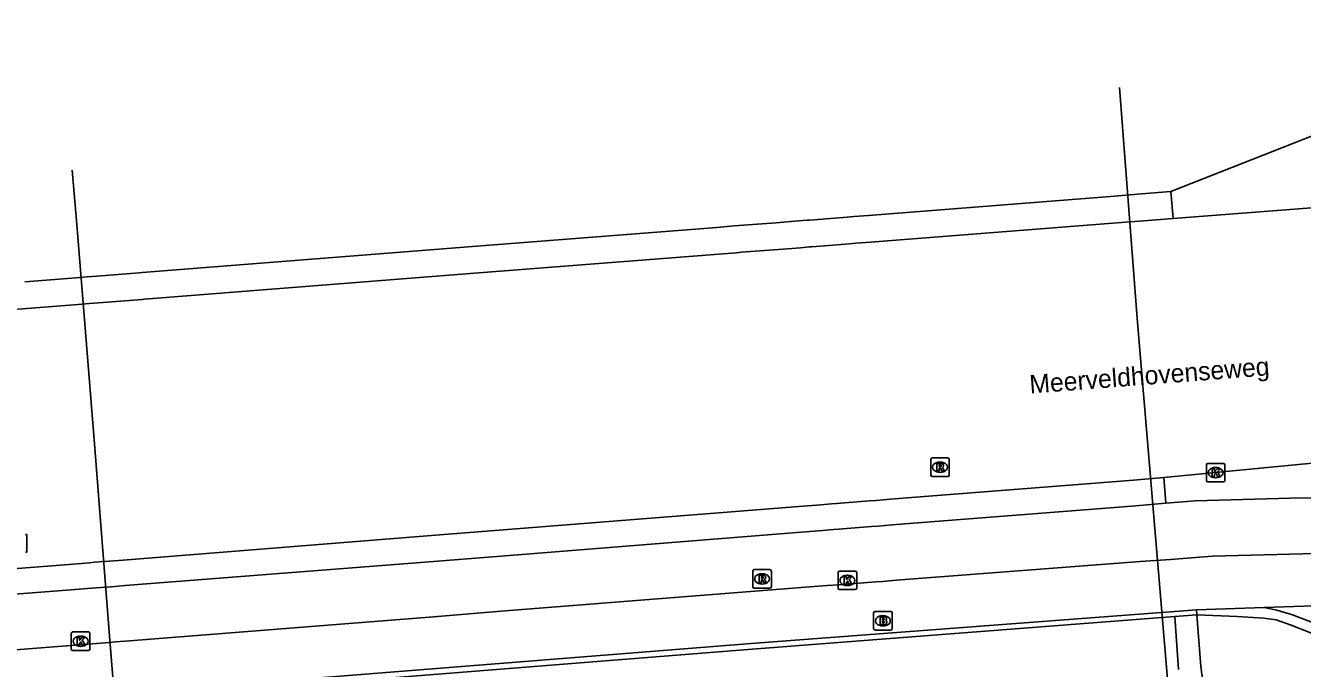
# Model space of a CAD drawing. Extents: x 157663 to 158496, y 379212 to 380934.
# Drawn here: x 157892.7 to 157961.7, y 380858 to 380892.7 of the extents above; entities that cross this region are included whole.
import ezdxf

# ---------------------------------------------------------------- set-up
doc = ezdxf.new("R2010")
doc.units = 0
for name, color, linetype in [('IMGEO_Berm_groen', 7, 'Continuous'), ('IMGEO_Berm_open', 7, 'Continuous'), ('IMGEO_Brandkraan', 7, 'Continuous'), ('IMGEO_Fietspad_gesloten', 7, 'Continuous'), ('IMGEO_Geluidsscherm', 7, 'Continuous'), ('IMGEO_Kolk', 7, 'Continuous'), ('IMGEO_Muur', 7, 'Continuous'), ('IMGEO_Openbare_ruimte_label', 7, 'Continuous'), ('IMGEO_Rijbaan_regionaal_gesloten', 7, 'Continuous'), ('IMGEO_Rioolput', 7, 'Continuous'), ('IMGEO_Terreindeel_gesloten', 7, 'Continuous'), ('IMGEO_Voetpad_open', 7, 'Continuous')]:
    doc.layers.add(name, color=color, linetype=linetype)

msp = doc.modelspace()

# ---------------------------------------------------------------- linework, layer by layer
at = {"layer": 'IMGEO_Berm_groen'}
for points in [[(157956.001, 380860.869), (157958.182, 380860.771), (157959.629, 380860.683), (157960.287, 380860.587), (157961.097, 380860.31), (157962.201, 380859.875), (157963.271, 380859.386), (157964.245, 380858.856), (157964.883, 380858.4), (157965.621, 380857.734), (157966.172, 380857.042), (157966.889, 380856.044), (157967.537, 380854.98), (157967.998, 380854.077), (157968.335, 380853.169), (157968.683, 380851.984), (157969.15, 380850.168)], [(157969.15, 380850.168), (157969.673, 380850.29), (157969.424, 380851.247), (157969.04, 380852.627), (157968.658, 380853.757), (157968.264, 380854.734), (157967.78, 380855.555), (157967.144, 380856.557), (157966.494, 380857.451), (157965.917, 380858.133), (157965.187, 380858.817), (157964.447, 380859.349), (157963.363, 380859.945), (157962.247, 380860.451), (157961.18, 380860.86), (157960.327, 380861.109), (157959.639, 380861.264)]]:
    msp.add_lwpolyline(points, dxfattribs=at)
at = {"layer": 'IMGEO_Berm_open'}
for points in [[(157954.819, 380860.777), (157931.957, 380859.016), (157909.091, 380857.181), (157878.581, 380854.843)], [(157956.001, 380860.869), (157954.819, 380860.777)], [(157955.012, 380857.901), (157954.819, 380860.777)], [(157956.959, 380852.419), (157956.217, 380858.075), (157956.001, 380860.869)]]:
    msp.add_lwpolyline(points, dxfattribs=at)
at = {"layer": 'IMGEO_Brandkraan'}
for p, q in [((157938.532, 380860.115), (157938.532, 380860.967)), ((157938.607, 380861.041), (157939.459, 380861.041)), ((157939.02, 380860.821), (157939.045, 380860.821)), ((157939.533, 380860.967), (157939.533, 380860.115)), ((157939.459, 380860.041), (157938.607, 380860.041)), ((157939.043, 380860.261), (157939.018, 380860.261))]:
    msp.add_line(p, q, dxfattribs=at)
for points in [[(157938.532, 380860.115), (157938.532, 380860.967)], [(157938.607, 380861.041), (157939.459, 380861.041)], [(157938.88, 380860.741), (157938.88, 380860.341), (157939.093, 380860.341)], [(157939.111, 380860.741), (157938.88, 380860.741)], [(157939.059, 380860.66), (157939.005, 380860.66), (157939.005, 380860.584)], [(157939.533, 380860.967), (157939.533, 380860.115)], [(157939.459, 380860.041), (157938.607, 380860.041)], [(157939.005, 380860.584), (157939.058, 380860.584)], [(157939.067, 380860.508), (157939.005, 380860.508), (157939.005, 380860.427)], [(157939.005, 380860.427), (157939.067, 380860.427)]]:
    msp.add_lwpolyline(points, dxfattribs=at)
for centre, radius, start, end in [((157938.609, 380860.965), 0.0765, 91.55205, 178.44795), ((157938.609, 380860.965), 0.0765, 91.55205, 178.44795), ((157939.06, 380860.622), 0.0379, 267.82845, 90.93552), ((157939.115, 380860.596), 0.145, 59.4692, 91.53667), ((157939.14, 380860.643), 0.0922, 285.51372, 58.15012), ((157939.457, 380860.965), 0.0765, 1.55205, 88.44795), ((157939.457, 380860.965), 0.0765, 1.55205, 88.44795), ((157938.609, 380860.117), 0.0765, 181.55205, 268.44795), ((157938.609, 380860.117), 0.0765, 181.55205, 268.44795), ((157939.068, 380860.467), 0.0404, 269.87594, 90.50774), ((157939.099, 380860.592), 0.251, 268.66757, 293.53466), ((157939.145, 380860.451), 0.105, 301.31148, 78.98903), ((157939.457, 380860.117), 0.0765, 271.55205, 358.44795), ((157939.457, 380860.117), 0.0765, 271.55205, 358.44795)]:
    msp.add_arc(centre, radius, start, end, dxfattribs=at)
for centre, major_axis, ratio, start_param, end_param in [((157939.019, 380860.541), (-0.387, 0.002), 0.722429, 4.712389, 7.853982), ((157939.044, 380860.541), (-0.39, 0.002), 0.717154, 1.570796, 4.712389)]:
    msp.add_ellipse(centre, major_axis=major_axis, ratio=ratio, start_param=start_param, end_param=end_param, dxfattribs=at)
at = {"layer": 'IMGEO_Fietspad_gesloten'}
for points in [[(157954.335, 380866.896), (157955.904, 380867.02), (157961.7, 380867.19), (157971.149, 380867.041), (157975.69, 380866.578), (157981.329, 380865.841), (157983.738, 380865.449), (157988.713, 380864.866), (157991.034, 380864.672), (157993.535, 380864.574), (157998.608, 380864.538), (158003.354, 380864.768), (158005.606, 380864.956), (158023.928, 380866.959), (158024.288, 380867.141), (158024.421, 380867.497), (158024.481, 380868.49)], [(157963.824, 380864.211), (157956.842, 380864.039), (157954.574, 380863.865), (157952.945, 380863.741), (157939.76, 380862.731), (157939.003, 380862.673), (157938.653, 380862.646), (157936.86, 380862.509), (157936.6, 380862.489), (157936.352, 380862.47), (157936.017, 380862.444), (157934.846, 380862.354), (157918.401, 380861.054), (157914.731, 380860.761), (157898.31, 380859.459), (157897.553, 380859.4), (157897.018, 380859.357), (157896.755, 380859.337), (157896.515, 380859.318), (157894.449, 380859.154), (157894.221, 380859.136), (157893.291, 380859.063), (157880.187, 380858.027)]]:
    msp.add_lwpolyline(points, dxfattribs=at)
at = {"layer": 'IMGEO_Geluidsscherm'}
for points in [[(157954.746, 380853.527), (157952.797, 380876.665), (157951.826, 380889.379)], [(157898.169, 380848.126), (157898.003, 380850.111), (157897.201, 380859.953), (157896.414, 380870.111), (157895.457, 380881.973), (157895.214, 380884.909)]]:
    msp.add_lwpolyline(points, dxfattribs=at)
at = {"layer": 'IMGEO_Kolk'}
for p, q in [((157956.519, 380868.127), (157956.519, 380868.979)), ((157956.594, 380869.053), (157957.446, 380869.053)), ((157957.52, 380868.979), (157957.52, 380868.127)), ((157957.03, 380868.273), (157957.005, 380868.273)), ((157957.007, 380868.833), (157957.032, 380868.833)), ((157957.446, 380868.053), (157956.594, 380868.053)), ((157936.615, 380862.3), (157936.615, 380863.152)), ((157936.69, 380863.226), (157937.542, 380863.226)), ((157937.103, 380863.006), (157937.128, 380863.006)), ((157937.616, 380863.152), (157937.616, 380862.3)), ((157937.542, 380862.226), (157936.69, 380862.226)), ((157937.126, 380862.446), (157937.101, 380862.446)), ((157895.162, 380859.013), (157895.162, 380859.865)), ((157895.237, 380859.939), (157896.089, 380859.939)), ((157895.65, 380859.719), (157895.675, 380859.719)), ((157896.163, 380859.865), (157896.163, 380859.013)), ((157896.089, 380858.939), (157895.237, 380858.939)), ((157895.673, 380859.159), (157895.648, 380859.159))]:
    msp.add_line(p, q, dxfattribs=at)
for points in [[(157956.519, 380868.127), (157956.519, 380868.979)], [(157956.594, 380869.053), (157957.446, 380869.053)], [(157957.52, 380868.979), (157957.52, 380868.127)], [(157956.84, 380868.753), (157956.963, 380868.753), (157956.963, 380868.602), (157957.093, 380868.753), (157957.257, 380868.753), (157957.111, 380868.602), (157957.264, 380868.353), (157957.112, 380868.353), (157957.027, 380868.517), (157956.963, 380868.45), (157956.963, 380868.353), (157956.84, 380868.353), (157956.84, 380868.753)], [(157957.446, 380868.053), (157956.594, 380868.053)], [(157936.615, 380862.3), (157936.615, 380863.152)], [(157936.69, 380863.226), (157937.542, 380863.226)], [(157936.936, 380862.926), (157937.059, 380862.926), (157937.059, 380862.775), (157937.189, 380862.926), (157937.353, 380862.926), (157937.207, 380862.775), (157937.36, 380862.526), (157937.208, 380862.526), (157937.123, 380862.69), (157937.059, 380862.623), (157937.059, 380862.526), (157936.936, 380862.526), (157936.936, 380862.926)], [(157937.616, 380863.152), (157937.616, 380862.3)], [(157937.542, 380862.226), (157936.69, 380862.226)], [(157895.162, 380859.013), (157895.162, 380859.865)], [(157895.237, 380859.939), (157896.089, 380859.939)], [(157895.483, 380859.639), (157895.606, 380859.639), (157895.606, 380859.488), (157895.736, 380859.639), (157895.9, 380859.639), (157895.754, 380859.488), (157895.907, 380859.239), (157895.755, 380859.239), (157895.67, 380859.403), (157895.606, 380859.336), (157895.606, 380859.239), (157895.483, 380859.239), (157895.483, 380859.639)], [(157896.163, 380859.865), (157896.163, 380859.013)], [(157896.089, 380858.939), (157895.237, 380858.939)]]:
    msp.add_lwpolyline(points, dxfattribs=at)
for centre, start, end in [((157956.596, 380868.977), 91.55205, 178.44795), ((157956.596, 380868.977), 91.55205, 178.44795), ((157957.444, 380868.977), 1.55205, 88.44795), ((157957.444, 380868.977), 1.55205, 88.44795), ((157956.596, 380868.129), 181.55205, 268.44795), ((157956.596, 380868.129), 181.55205, 268.44795), ((157957.444, 380868.129), 271.55205, 358.44795), ((157957.444, 380868.129), 271.55205, 358.44795), ((157936.692, 380863.15), 91.55205, 178.44795), ((157936.692, 380863.15), 91.55205, 178.44795), ((157937.54, 380863.15), 1.55205, 88.44795), ((157937.54, 380863.15), 1.55205, 88.44795), ((157936.692, 380862.302), 181.55205, 268.44795), ((157936.692, 380862.302), 181.55205, 268.44795), ((157937.54, 380862.302), 271.55205, 358.44795), ((157937.54, 380862.302), 271.55205, 358.44795), ((157895.239, 380859.863), 91.55205, 178.44795), ((157895.239, 380859.863), 91.55205, 178.44795), ((157896.087, 380859.863), 1.55205, 88.44795), ((157896.087, 380859.863), 1.55205, 88.44795), ((157895.239, 380859.015), 181.55205, 268.44795), ((157895.239, 380859.015), 181.55205, 268.44795), ((157896.087, 380859.015), 271.55205, 358.44795), ((157896.087, 380859.015), 271.55205, 358.44795)]:
    msp.add_arc(centre, 0.0765, start, end, dxfattribs=at)
for centre, major_axis, ratio, start_param, end_param in [((157957.006, 380868.553), (-0.387, 0.002), 0.722429, 4.712389, 7.853982), ((157957.031, 380868.553), (-0.39, 0.002), 0.717154, 1.570796, 4.712389), ((157937.102, 380862.726), (-0.387, 0.002), 0.722429, 4.712389, 7.853982), ((157937.127, 380862.726), (-0.39, 0.002), 0.717154, 1.570796, 4.712389), ((157895.649, 380859.439), (-0.387, 0.002), 0.722429, 4.712389, 7.853982), ((157895.674, 380859.439), (-0.39, 0.002), 0.717154, 1.570796, 4.712389)]:
    msp.add_ellipse(centre, major_axis=major_axis, ratio=ratio, start_param=start_param, end_param=end_param, dxfattribs=at)
at = {"layer": 'IMGEO_Muur'}
for points in [[(157892.649, 380878.876), (157892.882, 380878.894), (157894.948, 380879.056), (157895.183, 380879.075), (157895.408, 380879.092), (157896.018, 380879.14), (157896.773, 380879.2), (157898.837, 380879.362), (157898.988, 380879.374), (157899.917, 380879.447), (157913.19, 380880.491), (157916.84, 380880.778), (157930.053, 380881.817), (157931.001, 380881.892), (157931.251, 380881.911), (157933.265, 380882.07), (157934.476, 380882.165), (157934.953, 380882.202), (157935.054, 380882.21), (157935.315, 380882.231), (157937.108, 380882.372), (157937.456, 380882.399), (157938.249, 380882.462), (157951.341, 380883.491), (157953.01, 380883.622), (157954.594, 380883.747)], [(157954.594, 380883.747), (157954.724, 380882.301)], [(157954.724, 380882.301), (157953.125, 380882.175), (157951.458, 380882.044), (157938.36, 380881.015), (157937.57, 380880.953), (157937.221, 380880.925), (157935.428, 380880.784), (157935.167, 380880.764), (157935.068, 380880.756), (157934.586, 380880.718), (157933.381, 380880.623), (157931.375, 380880.466), (157931.116, 380880.445), (157930.167, 380880.371), (157916.954, 380879.332), (157913.303, 380879.045), (157900.032, 380878.002), (157899.104, 380877.929), (157898.984, 380877.92), (157896.885, 380877.755), (157896.13, 380877.695), (157895.526, 380877.648), (157895.298, 380877.63), (157895.063, 380877.612), (157892.997, 380877.449), (157892.764, 380877.431), (157891.803, 380877.355)], [(157877.989, 380862.246), (157879.843, 380862.393), (157892.936, 380863.429), (157893.873, 380863.504), (157894.102, 380863.522), (157896.168, 380863.685), (157896.407, 380863.704), (157896.662, 380863.724), (157897.204, 380863.767), (157897.97, 380863.828), (157914.39, 380865.128), (157918.056, 380865.418), (157934.496, 380866.72), (157935.669, 380866.813), (157936.05, 380866.843), (157936.257, 380866.86), (157936.517, 380866.88), (157938.31, 380867.022), (157938.66, 380867.05), (157939.424, 380867.11), (157952.586, 380868.153), (157954.225, 380868.282)], [(157954.225, 380868.282), (157954.335, 380866.896)], [(157954.335, 380866.896), (157952.699, 380866.766), (157939.53, 380865.725), (157938.768, 380865.665), (157938.419, 380865.637), (157936.626, 380865.495), (157936.366, 380865.474), (157936.146, 380865.457), (157935.779, 380865.428), (157934.607, 380865.335), (157918.166, 380864.024), (157914.499, 380863.731), (157898.077, 380862.444), (157897.311, 380862.385), (157896.774, 380862.343), (157896.517, 380862.323), (157896.278, 380862.304), (157894.211, 380862.144), (157893.983, 380862.127), (157893.048, 380862.054), (157879.95, 380861.039), (157878.097, 380860.895)]]:
    msp.add_lwpolyline(points, dxfattribs=at)
at = {"layer": 'IMGEO_Rijbaan_regionaal_gesloten'}
for points in [[(157994.262, 380892.73), (157997.961, 380892.394), (158002.515, 380891.634), (158005.294, 380890.988), (158005.897, 380890.638), (158006.263, 380890.295), (158006.548, 380889.8), (158006.677, 380889.061), (158006.66, 380888.281), (158006.463, 380887.58), (158005.812, 380886.859), (158005.095, 380886.433), (158004.043, 380886.272), (157973.624, 380883.877), (157967.818, 380883.31), (157954.724, 380882.301)], [(157954.594, 380883.747), (157971.776, 380890.513), (157973.266, 380891.072)], [(157954.225, 380868.282), (157965.228, 380869.346), (157973.664, 380869.772), (157977.541, 380870.042), (157990.931, 380871.088), (158004.097, 380872.247), (158012.082, 380873.112), (158016.017, 380873.638), (158022.999, 380874.809)]]:
    msp.add_lwpolyline(points, dxfattribs=at)
at = {"layer": 'IMGEO_Rioolput'}
for p, q in [((157941.62, 380868.422), (157941.62, 380869.274)), ((157941.695, 380869.348), (157942.547, 380869.348)), ((157942.108, 380869.128), (157942.133, 380869.128)), ((157942.621, 380869.274), (157942.621, 380868.422)), ((157942.547, 380868.348), (157941.695, 380868.348)), ((157942.131, 380868.568), (157942.106, 380868.568)), ((157892.761, 380865.158), (157892.761, 380864.306)), ((157932.001, 380862.381), (157932.001, 380863.233)), ((157932.076, 380863.307), (157932.928, 380863.307)), ((157932.489, 380863.087), (157932.514, 380863.087)), ((157933.002, 380863.233), (157933.002, 380862.381)), ((157932.928, 380862.307), (157932.076, 380862.307)), ((157932.512, 380862.527), (157932.487, 380862.527))]:
    msp.add_line(p, q, dxfattribs=at)
for points in [[(157941.62, 380868.422), (157941.62, 380869.274)], [(157941.695, 380869.348), (157942.547, 380869.348)], [(157942.209, 380869.046), (157941.957, 380869.048), (157941.957, 380868.648)], [(157942.135, 380868.967), (157942.081, 380868.967), (157942.081, 380868.886)], [(157942.621, 380869.274), (157942.621, 380868.422)], [(157942.547, 380868.348), (157941.695, 380868.348)], [(157941.957, 380868.648), (157942.081, 380868.648), (157942.081, 380868.81), (157942.092, 380868.81)], [(157942.081, 380868.886), (157942.133, 380868.886)], [(157942.139, 380868.781), (157942.21, 380868.648), (157942.35, 380868.648), (157942.285, 380868.774)], [(157892.761, 380865.158), (157892.761, 380864.306)], [(157932.001, 380862.381), (157932.001, 380863.233)], [(157932.076, 380863.307), (157932.928, 380863.307)], [(157932.59, 380863.005), (157932.338, 380863.007), (157932.338, 380862.607)], [(157932.338, 380862.607), (157932.462, 380862.607), (157932.462, 380862.769), (157932.473, 380862.769)], [(157932.516, 380862.926), (157932.462, 380862.926), (157932.462, 380862.845)], [(157932.462, 380862.845), (157932.514, 380862.845)], [(157932.52, 380862.74), (157932.591, 380862.607), (157932.731, 380862.607), (157932.666, 380862.733)], [(157933.002, 380863.233), (157933.002, 380862.381)], [(157932.928, 380862.307), (157932.076, 380862.307)]]:
    msp.add_lwpolyline(points, dxfattribs=at)
for centre, radius, start, end in [((157941.697, 380869.272), 0.0765, 91.55205, 178.44795), ((157941.697, 380869.272), 0.0765, 91.55205, 178.44795), ((157942.141, 380868.871), 0.0964, 77.00612, 93.18647), ((157942.155, 380868.928), 0.0378, 276.66336, 79.67722), ((157942.208, 380868.936), 0.109, 350.36119, 89.41601), ((157942.545, 380869.272), 0.0765, 1.55205, 88.44795), ((157942.545, 380869.272), 0.0765, 1.55205, 88.44795), ((157941.697, 380868.424), 0.0765, 181.55205, 268.44795), ((157941.697, 380868.424), 0.0765, 181.55205, 268.44795), ((157942.091, 380868.757), 0.0533, 26.02933, 88.69889), ((157942.117, 380869.075), 0.19, 274.7715, 282.96867), ((157942.206, 380868.936), 0.112, 277.58423, 350.98172), ((157942.19, 380868.721), 0.108, 29.51342, 73.79051), ((157942.545, 380868.424), 0.0765, 271.55205, 358.44795), ((157942.545, 380868.424), 0.0765, 271.55205, 358.44795), ((157892.685, 380865.156), 0.0765, 1.55205, 88.44795), ((157892.685, 380865.156), 0.0765, 1.55205, 88.44795), ((157892.685, 380864.308), 0.0765, 271.55205, 358.44795), ((157892.685, 380864.308), 0.0765, 271.55205, 358.44795), ((157932.078, 380863.231), 0.0765, 91.55205, 178.44795), ((157932.078, 380863.231), 0.0765, 91.55205, 178.44795), ((157932.472, 380862.716), 0.0533, 26.02933, 88.69889), ((157932.498, 380863.034), 0.19, 274.7715, 282.96867), ((157932.522, 380862.83), 0.0964, 77.00612, 93.18647), ((157932.536, 380862.887), 0.0378, 276.66336, 79.67722), ((157932.589, 380862.895), 0.109, 350.36119, 89.41601), ((157932.587, 380862.895), 0.112, 277.58423, 350.98172), ((157932.571, 380862.68), 0.108, 29.51342, 73.79051), ((157932.926, 380863.231), 0.0765, 1.55205, 88.44795), ((157932.926, 380863.231), 0.0765, 1.55205, 88.44795), ((157932.078, 380862.383), 0.0765, 181.55205, 268.44795), ((157932.078, 380862.383), 0.0765, 181.55205, 268.44795), ((157932.926, 380862.383), 0.0765, 271.55205, 358.44795), ((157932.926, 380862.383), 0.0765, 271.55205, 358.44795)]:
    msp.add_arc(centre, radius, start, end, dxfattribs=at)
for centre, major_axis, ratio, start_param, end_param in [((157942.107, 380868.848), (-0.387, 0.002), 0.722429, 4.712389, 7.853982), ((157942.132, 380868.848), (-0.39, 0.002), 0.717154, 1.570796, 4.712389), ((157932.488, 380862.807), (-0.387, 0.002), 0.722429, 4.712389, 7.853982), ((157932.513, 380862.807), (-0.39, 0.002), 0.717154, 1.570796, 4.712389)]:
    msp.add_ellipse(centre, major_axis=major_axis, ratio=ratio, start_param=start_param, end_param=end_param, dxfattribs=at)
at = {"layer": 'IMGEO_Terreindeel_gesloten'}
msp.add_lwpolyline([(157955.98, 380861.143), (157956.001, 380860.869)], dxfattribs=at)
at = {"layer": 'IMGEO_Voetpad_open'}
for points in [[(158025.566, 380861.152), (158024.169, 380861.037), (158021.44, 380860.757), (158017.369, 380860.33), (158012.951, 380859.817), (158008.758, 380859.349), (158004.641, 380858.972), (158002.748, 380858.831), (158001.42, 380858.743), (158000.32, 380858.63), (157997.501, 380858.609), (157994.18, 380858.618), (157990.574, 380858.754), (157988.149, 380858.926), (157985.93, 380859.195), (157983.505, 380859.542), (157980.174, 380859.997), (157973.623, 380860.945), (157963.388, 380861.388), (157959.639, 380861.264)], [(157955.98, 380861.143), (157955.525, 380861.105), (157931.915, 380859.307), (157909.012, 380857.491), (157877.345, 380854.986)], [(157959.639, 380861.264), (157955.98, 380861.143)]]:
    msp.add_lwpolyline(points, dxfattribs=at)

# ---------------------------------------------------------------- texts
at = {"layer": 'IMGEO_Openbare_ruimte_label'}
msp.add_text('Meerveldhovenseweg', height=1, rotation=4.35915, dxfattribs=at).set_placement((157946.989, 380872.827))

doc.saveas('drawing.dxf')
